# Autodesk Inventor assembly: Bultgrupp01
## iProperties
Shininess: 64.0
Angle Display Precision: 2
Document Length Units: 11269
Document Angle Units: 11279
Document Time Units: 11290
Document Mass Units: 11283
Document Length Units Precision: 3
Document Angle Units Precision: 2
Created: 2001-12
Part Number: Bultgrupp01
Document SubType Name: Assembly
Designer: Tobben
Density: 0.0
Volumn: 0.0
Area: 0.0
PropertySet Name: Model Information
Control State: 0
Master: False
Checked Out: False
Author: Tobben
